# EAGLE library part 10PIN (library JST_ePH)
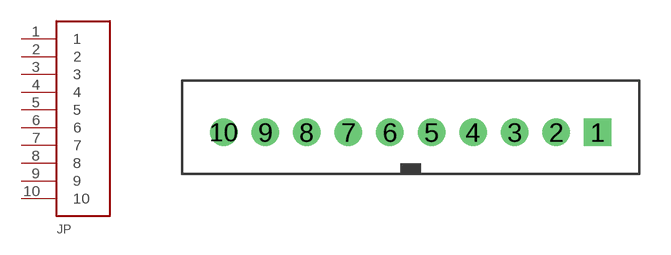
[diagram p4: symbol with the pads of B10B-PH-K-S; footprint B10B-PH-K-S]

Designator prefix JP

## 10PIN  [B10B-PH-K-S]
1  1
2  2
3  3
4  4
5  5
6  6
7  7
8  8
9  9
10  10

## Footprint B10B-PH-K-S (pad centres in mm)
drill 0.813 square: 1 9,0
drill 0.813 round: 2 7,0; 3 5,0; 4 3,0; 5 1,0; 6 -1,0; 7 -3,0; 8 -5,0; 9 -7,0; 10 -9,0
